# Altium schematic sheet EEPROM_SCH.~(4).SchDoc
size D
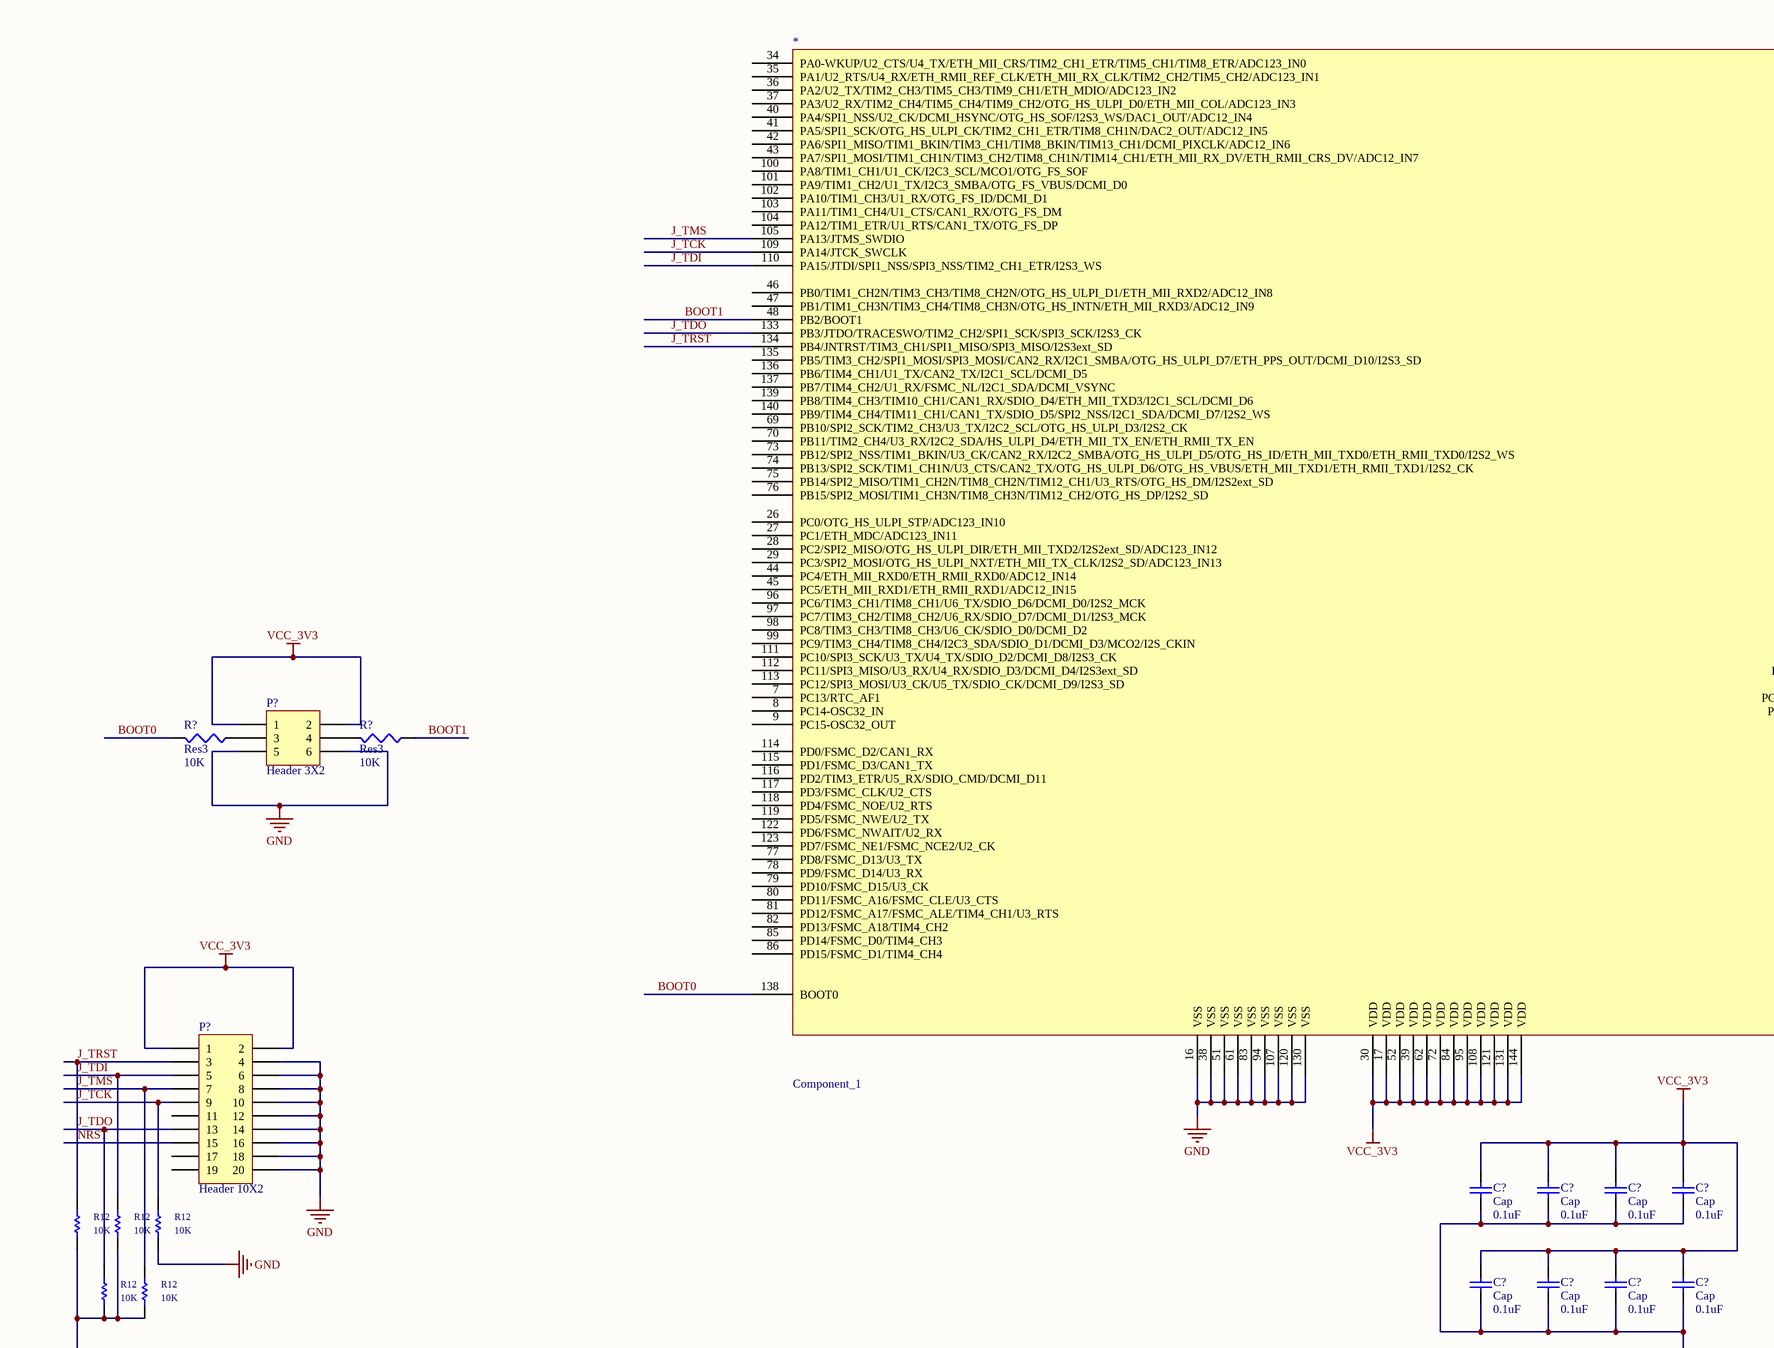
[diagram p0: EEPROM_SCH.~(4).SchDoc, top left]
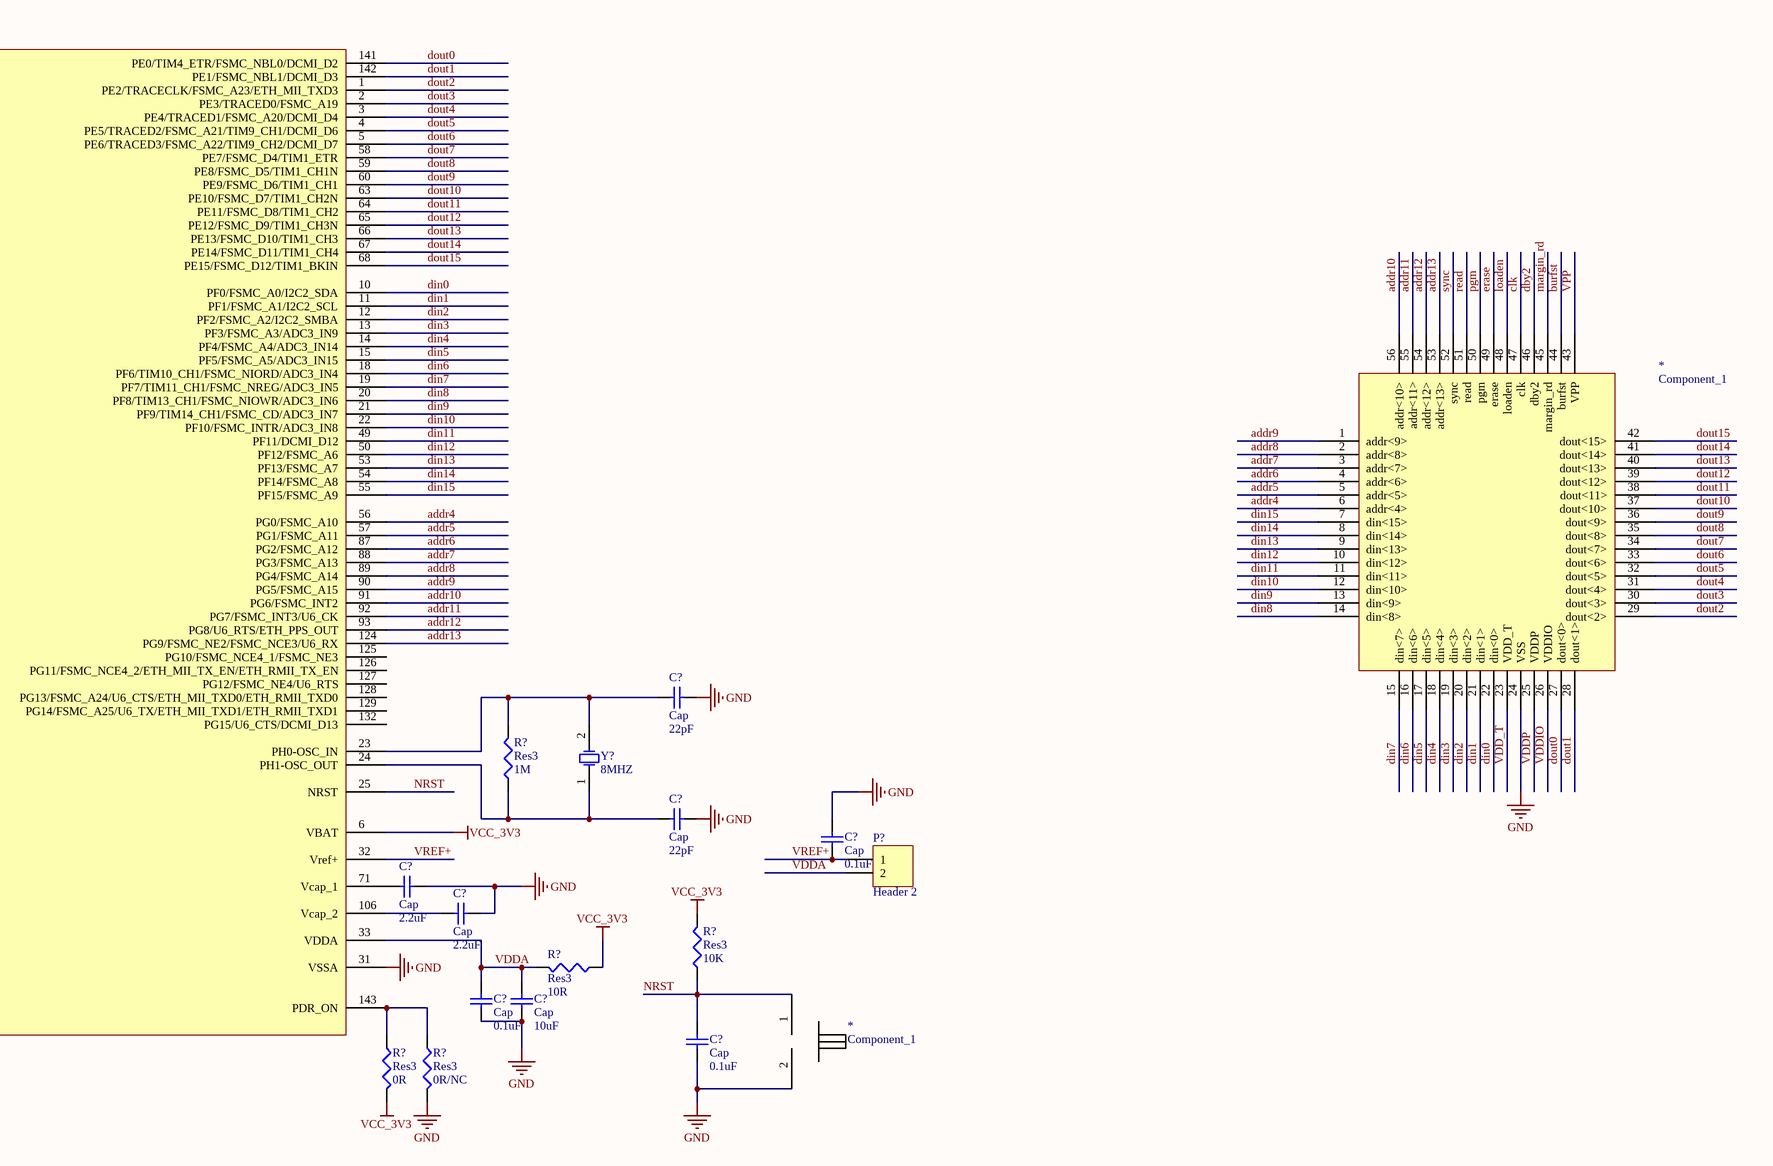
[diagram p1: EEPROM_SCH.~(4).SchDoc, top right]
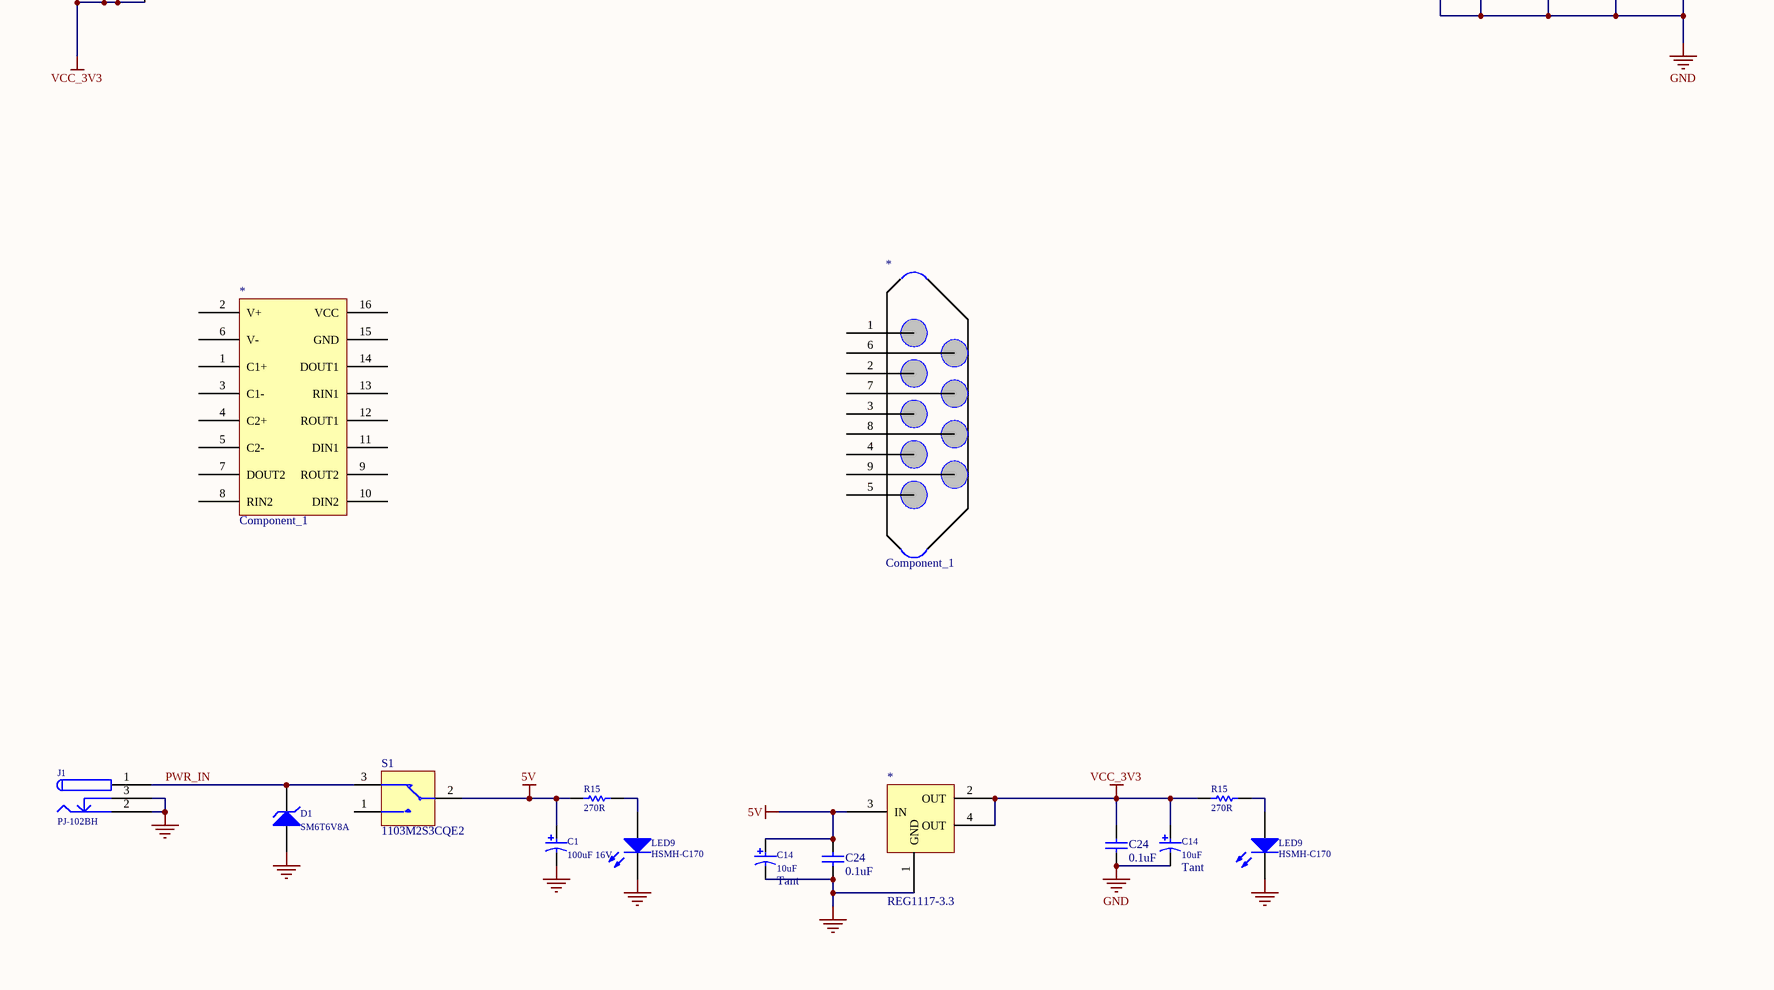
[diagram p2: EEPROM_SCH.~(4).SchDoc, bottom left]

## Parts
(Parts that share a designator on the sheet are numbered #1, #2 ... from top to bottom, then left to right.)
*#1  Component_1  [STM32F407ZET6_LCC144]
*#2  Component_1
*#3  Component_1
*#4  Component_1
*#5  Component_1
*#6  REG1117-3.3  [PCBComponent_1]
C1  100uF 16V  [CAPPR2-5X6.8]
C14#1  10uF  Capacitor Type: Tant  [MCCT-B]
C14#2  10uF  Capacitor Type: Tant  [MCCT-B]
C24#1  0.1uF  [CC2012-0805]
C24#2  0.1uF  [CC2012-0805]
C?#1  Cap  value 22pF  [RAD-0.3]
C?#2  Cap  value 22pF  [RAD-0.3]
C?#3  Cap  value 0.1uF  [RAD-0.3]
C?#4  Cap  value 2.2uF  [RAD-0.3]
C?#5  Cap  value 2.2uF  [RAD-0.3]
C?#6  Cap  value 0.1uF  [RAD-0.3]
C?#7  Cap  value 10uF  [RAD-0.3]
C?#8  Cap  value 0.1uF  [RAD-0.3]
C?#9  Cap  value 0.1uF  [RAD-0.3]
C?#10  Cap  value 0.1uF  [RAD-0.3]
C?#11  Cap  value 0.1uF  [RAD-0.3]
C?#12  Cap  value 0.1uF  [RAD-0.3]
C?#13  Cap  value 0.1uF  [RAD-0.3]
C?#14  Cap  value 0.1uF  [RAD-0.3]
C?#15  Cap  value 0.1uF  [RAD-0.3]
C?#16  Cap  value 0.1uF  [RAD-0.3]
D1  SM6T6V8A  [PCBComponent_1]
J1  PJ-102BH  [PCBComponent_1]
LED9#1  HSMH-C170  [SMD _LED]
LED9#2  HSMH-C170  [SMD _LED]
P?#1  Header 3X2  [PCBComponent_1]
P?#2  Header 2  [HDR1X2]
P?#3  Header 10X2  [HDR2X10]
R12#1  10K  [CC2012-0805]
R12#2  10K  [CC2012-0805]
R12#3  10K  [CC2012-0805]
R12#4  10K  [CC2012-0805]
R12#5  10K  [CC2012-0805]
R15#1  270R  [CR2012-0805]
R15#2  270R  [CR2012-0805]
R?#1  Res3  value 10K  [J1-0603]
R?#2  Res3  value 10K  [J1-0603]
R?#3  Res3  value 1M  [J1-0603]
R?#4  Res3  value 10K  [J1-0603]
R?#5  Res3  value 10R  [J1-0603]
R?#6  Res3  value 0R  [J1-0603]
R?#7  Res3  value 0R/NC  [J1-0603]
S1  1103M2S3CQE2  [PCBComponent_1]
Y?  8MHZ  [R38]

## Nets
5V: *#6.3(IN) C1.1 C14#2.1 C24#2.2 R15#1.2 S1.2
GND: *#1.16(VSS) *#1.31(VSSA) *#1.38(VSS) *#1.51(VSS) *#1.61(VSS) *#1.83(VSS) *#1.94(VSS) *#1.107(VSS) *#1.120(VSS) *#1.130(VSS) *#2.24(VSS) *#3.2 *#6.1(GND) C1.2 C14#1.2 C14#2.2 C24#1.1 C24#2.1 C?#1.1 C?#2.1 C?#3.1 C?#4.2 C?#5.2 C?#6.2 C?#7.2 C?#8.2 C?#9.1 C?#10.1 C?#11.1 C?#12.1 C?#13.1 C?#14.1 C?#15.1 C?#16.1 D1.1(A) J1.2 J1.3 LED9#1.2(K) LED9#2.2(K) P?#1.5 P?#1.6 P?#3.4 P?#3.6 P?#3.8 P?#3.10 P?#3.12 P?#3.14 P?#3.16 P?#3.18 P?#3.20 R12#3.2 R?#7.2
VCC_3V3: *#1.6(VBAT) *#1.17(VDD) *#1.30(VDD) *#1.39(VDD) *#1.52(VDD) *#1.62(VDD) *#1.72(VDD) *#1.84(VDD) *#1.95(VDD) *#1.108(VDD) *#1.121(VDD) *#1.131(VDD) *#1.144(VDD) *#6.2(OUT) *#6.4(OUT) C14#1.1 C24#1.2 C?#9.2 C?#10.2 C?#11.2 C?#12.2 C?#13.2 C?#14.2 C?#15.2 C?#16.2 P?#1.1 P?#1.2 P?#3.1 P?#3.2 R12#1.2 R12#2.2 R12#4.2 R12#5.2 R15#2.2 R?#4.2 R?#5.1 R?#6.2
addr4: *#1.56(PG0/FSMC_A10) *#2.6(addr<4>)
addr5: *#1.57(PG1/FSMC_A11) *#2.5(addr<5>)
addr6: *#1.87(PG2/FSMC_A12) *#2.4(addr<6>)
addr7: *#1.88(PG3/FSMC_A13) *#2.3(addr<7>)
addr8: *#1.89(PG4/FSMC_A14) *#2.2(addr<8>)
addr9: *#1.90(PG5/FSMC_A15) *#2.1(addr<9>)
addr10: *#1.91(PG6/FSMC_INT2) *#2.56(addr<10>)
addr11: *#1.92(PG7/FSMC_INT3/U6_CK) *#2.55(addr<11>)
addr12: *#1.93(PG8/U6_RTS/ETH_PPS_OUT) *#2.54(addr<12>)
addr13: *#1.124(PG9/FSMC_NE2/FSMC_NCE3/U6_RX) *#2.53(addr<13>)
BOOT0: *#1.138(BOOT0) R?#1.2
BOOT1: *#1.48(PB2/BOOT1) R?#2.1
burfst: *#2.44(burfst)
clk: *#2.47(clk)
dby2: *#2.46(dby2)
din0: *#1.10(PF0/FSMC_A0/I2C2_SDA) *#2.22(din<0>)
din1: *#1.11(PF1/FSMC_A1/I2C2_SCL) *#2.21(din<1>)
din2: *#1.12(PF2/FSMC_A2/I2C2_SMBA) *#2.20(din<2>)
din3: *#1.13(PF3/FSMC_A3/ADC3_IN9) *#2.19(din<3>)
din4: *#1.14(PF4/FSMC_A4/ADC3_IN14) *#2.18(din<4>)
din5: *#1.15(PF5/FSMC_A5/ADC3_IN15) *#2.17(din<5>)
din6: *#1.18(PF6/TIM10_CH1/FSMC_NIORD/ADC3_IN4) *#2.16(din<6>)
din7: *#1.19(PF7/TIM11_CH1/FSMC_NREG/ADC3_IN5) *#2.15(din<7>)
din8: *#1.20(PF8/TIM13_CH1/FSMC_NIOWR/ADC3_IN6) *#2.14(din<8>)
din9: *#1.21(PF9/TIM14_CH1/FSMC_CD/ADC3_IN7) *#2.13(din<9>)
din10: *#1.22(PF10/FSMC_INTR/ADC3_IN8) *#2.12(din<10>)
din11: *#1.49(PF11/DCMI_D12) *#2.11(din<11>)
din12: *#1.50(PF12/FSMC_A6) *#2.10(din<12>)
din13: *#1.53(PF13/FSMC_A7) *#2.9(din<13>)
din14: *#1.54(PF14/FSMC_A8) *#2.8(din<14>)
din15: *#1.55(PF15/FSMC_A9) *#2.7(din<15>)
dout0: *#1.141(PE0/TIM4_ETR/FSMC_NBL0/DCMI_D2) *#2.27(dout<0>)
dout1: *#1.142(PE1/FSMC_NBL1/DCMI_D3) *#2.28(dout<1>)
dout2: *#1.1(PE2/TRACECLK/FSMC_A23/ETH_MII_TXD3) *#2.29(dout<2>)
dout3: *#1.2(PE3/TRACED0/FSMC_A19) *#2.30(dout<3>)
dout4: *#1.3(PE4/TRACED1/FSMC_A20/DCMI_D4) *#2.31(dout<4>)
dout5: *#1.4(PE5/TRACED2/FSMC_A21/TIM9_CH1/DCMI_D6) *#2.32(dout<5>)
dout6: *#1.5(PE6/TRACED3/FSMC_A22/TIM9_CH2/DCMI_D7) *#2.33(dout<6>)
dout7: *#1.58(PE7/FSMC_D4/TIM1_ETR) *#2.34(dout<7>)
dout8: *#1.59(PE8/FSMC_D5/TIM1_CH1N) *#2.35(dout<8>)
dout9: *#1.60(PE9/FSMC_D6/TIM1_CH1) *#2.36(dout<9>)
dout10: *#1.63(PE10/FSMC_D7/TIM1_CH2N) *#2.37(dout<10>)
dout11: *#1.64(PE11/FSMC_D8/TIM1_CH2) *#2.38(dout<11>)
dout12: *#1.65(PE12/FSMC_D9/TIM1_CH3N) *#2.39(dout<12>)
dout13: *#1.66(PE13/FSMC_D10/TIM1_CH3) *#2.40(dout<13>)
dout14: *#1.67(PE14/FSMC_D11/TIM1_CH4) *#2.41(dout<14>)
dout15: *#1.68(PE15/FSMC_D12/TIM1_BKIN) *#2.42(dout<15>)
erase: *#2.49(erase)
J_TCK: *#1.25(NRST) *#1.105(PA13/JTMS_SWDIO) *#1.109(PA14/JTCK_SWCLK) *#1.110(PA15/JTDI/SPI1_NSS/SPI3_NSS/TIM2_CH1_ETR/I2S3_WS) *#1.133(PB3/JTDO/TRACESWO/TIM2_CH2/SPI1_SCK/SPI3_SCK/I2S3_CK) *#1.134(PB4/JNTRST/TIM3_CH1/SPI1_MISO/SPI3_MISO/I2S3ext_SD) *#3.1 C?#8.1 P?#3.3 P?#3.5 P?#3.7 P?#3.9 P?#3.13 P?#3.15 R12#1.1 R12#2.1 R12#3.1 R12#4.1 R12#5.1 R?#4.1  [also labelled J_TDI, J_TDO, J_TMS, J_TRST, NRST]
loaden: *#2.48(loaden)
margin_rd: *#2.45(margin_rd)
pgm: *#2.50(pgm)
PWR_IN: D1.2(K) J1.1 S1.3
read: *#2.51(read)
sync: *#2.52(sync)
VDD_T: *#2.23(VDD_T)
VDDA: *#1.33(VDDA) C?#6.1 C?#7.1 P?#2.2 R?#5.2
VDDIO: *#2.26(VDDIO)
VDDP: *#2.25(VDDP)
VPP: *#2.43(VPP)
VREF+: *#1.32(Vref+) C?#3.2 P?#2.1
Net*#1_23: *#1.23(PH0-OSC_IN) C?#1.2 R?#3.2 Y?.2(OSC2)
Net*#1_24: *#1.24(PH1-OSC_OUT) C?#2.2 R?#3.1 Y?.1(OSC1)
Net*#1_71: *#1.71(Vcap_1) C?#4.1
Net*#1_106: *#1.106(Vcap_2) C?#5.1
Net*#1_143: *#1.143(PDR_ON) R?#6.1 R?#7.1
NetLED9#1_1: LED9#1.1(A) R15#1.1
NetLED9#2_1: LED9#2.1(A) R15#2.1
NetP?#1_3: P?#1.3 R?#1.1
NetP?#1_4: P?#1.4 R?#2.2

Not connected (* = marked no-connect by the designer): *#1 7(PC13/RTC_AF1) 8(PC14-OSC32_IN) 9(PC15-OSC32_OUT) 26(PC0/OTG_HS_ULPI_STP/ADC123_IN10) 27(PC1/ETH_MDC/ADC123_IN11) 28(PC2/SPI2_MISO/OTG_HS_ULPI_DIR/ETH_MII_TXD2/I2S2ext_SD/ADC123_IN12) 29(PC3/SPI2_MOSI/OTG_HS_ULPI_NXT/ETH_MII_TX_CLK/I2S2_SD/ADC123_IN13) 34(PA0-WKUP/U2_CTS/U4_TX/ETH_MII_CRS/TIM2_CH1_ETR/TIM5_CH1/TIM8_ETR/ADC123_IN0) 35(PA1/U2_RTS/U4_RX/ETH_RMII_REF_CLK/ETH_MII_RX_CLK/TIM2_CH2/TIM5_CH2/ADC123_IN1) 36(PA2/U2_TX/TIM2_CH3/TIM5_CH3/TIM9_CH1/ETH_MDIO/ADC123_IN2) 37(PA3/U2_RX/TIM2_CH4/TIM5_CH4/TIM9_CH2/OTG_HS_ULPI_D0/ETH_MII_COL/ADC123_IN3) 40(PA4/SPI1_NSS/U2_CK/DCMI_HSYNC/OTG_HS_SOF/I2S3_WS/DAC1_OUT/ADC12_IN4) 41(PA5/SPI1_SCK/OTG_HS_ULPI_CK/TIM2_CH1_ETR/TIM8_CH1N/DAC2_OUT/ADC12_IN5) 42(PA6/SPI1_MISO/TIM1_BKIN/TIM3_CH1/TIM8_BKIN/TIM13_CH1/DCMI_PIXCLK/ADC12_IN6) 43(PA7/SPI1_MOSI/TIM1_CH1N/TIM3_CH2/TIM8_CH1N/TIM14_CH1/ETH_MII_RX_DV/ETH_RMII_CRS_DV/ADC12_IN7) 44(PC4/ETH_MII_RXD0/ETH_RMII_RXD0/ADC12_IN14) 45(PC5/ETH_MII_RXD1/ETH_RMII_RXD1/ADC12_IN15) 46(PB0/TIM1_CH2N/TIM3_CH3/TIM8_CH2N/OTG_HS_ULPI_D1/ETH_MII_RXD2/ADC12_IN8) 47(PB1/TIM1_CH3N/TIM3_CH4/TIM8_CH3N/OTG_HS_INTN/ETH_MII_RXD3/ADC12_IN9) 69(PB10/SPI2_SCK/TIM2_CH3/U3_TX/I2C2_SCL/OTG_HS_ULPI_D3/I2S2_CK) 70(PB11/TIM2_CH4/U3_RX/I2C2_SDA/HS_ULPI_D4/ETH_MII_TX_EN/ETH_RMII_TX_EN) 73(PB12/SPI2_NSS/TIM1_BKIN/U3_CK/CAN2_RX/I2C2_SMBA/OTG_HS_ULPI_D5/OTG_HS_ID/ETH_MII_TXD0/ETH_RMII_TXD0/I2S2_WS) 74(PB13/SPI2_SCK/TIM1_CH1N/U3_CTS/CAN2_TX/OTG_HS_ULPI_D6/OTG_HS_VBUS/ETH_MII_TXD1/ETH_RMII_TXD1/I2S2_CK) 75(PB14/SPI2_MISO/TIM1_CH2N/TIM8_CH2N/TIM12_CH1/U3_RTS/OTG_HS_DM/I2S2ext_SD) 76(PB15/SPI2_MOSI/TIM1_CH3N/TIM8_CH3N/TIM12_CH2/OTG_HS_DP/I2S2_SD) 77(PD8/FSMC_D13/U3_TX) 78(PD9/FSMC_D14/U3_RX) 79(PD10/FSMC_D15/U3_CK) 80(PD11/FSMC_A16/FSMC_CLE/U3_CTS) 81(PD12/FSMC_A17/FSMC_ALE/TIM4_CH1/U3_RTS) 82(PD13/FSMC_A18/TIM4_CH2) 85(PD14/FSMC_D0/TIM4_CH3) 86(PD15/FSMC_D1/TIM4_CH4) 96(PC6/TIM3_CH1/TIM8_CH1/U6_TX/SDIO_D6/DCMI_D0/I2S2_MCK) 97(PC7/TIM3_CH2/TIM8_CH2/U6_RX/SDIO_D7/DCMI_D1/I2S3_MCK) 98(PC8/TIM3_CH3/TIM8_CH3/U6_CK/SDIO_D0/DCMI_D2) 99(PC9/TIM3_CH4/TIM8_CH4/I2C3_SDA/SDIO_D1/DCMI_D3/MCO2/I2S_CKIN) 100(PA8/TIM1_CH1/U1_CK/I2C3_SCL/MCO1/OTG_FS_SOF) 101(PA9/TIM1_CH2/U1_TX/I2C3_SMBA/OTG_FS_VBUS/DCMI_D0) 102(PA10/TIM1_CH3/U1_RX/OTG_FS_ID/DCMI_D1) 103(PA11/TIM1_CH4/U1_CTS/CAN1_RX/OTG_FS_DM) 104(PA12/TIM1_ETR/U1_RTS/CAN1_TX/OTG_FS_DP) 111(PC10/SPI3_SCK/U3_TX/U4_TX/SDIO_D2/DCMI_D8/I2S3_CK) 112(PC11/SPI3_MISO/U3_RX/U4_RX/SDIO_D3/DCMI_D4/I2S3ext_SD) 113(PC12/SPI3_MOSI/U3_CK/U5_TX/SDIO_CK/DCMI_D9/I2S3_SD) 114(PD0/FSMC_D2/CAN1_RX) 115(PD1/FSMC_D3/CAN1_TX) 116(PD2/TIM3_ETR/U5_RX/SDIO_CMD/DCMI_D11) 117(PD3/FSMC_CLK/U2_CTS) 118(PD4/FSMC_NOE/U2_RTS) 119(PD5/FSMC_NWE/U2_TX) 122(PD6/FSMC_NWAIT/U2_RX) 123(PD7/FSMC_NE1/FSMC_NCE2/U2_CK) 125(PG10/FSMC_NCE4_1/FSMC_NE3) 126(PG11/FSMC_NCE4_2/ETH_MII_TX_EN/ETH_RMII_TX_EN) 127(PG12/FSMC_NE4/U6_RTS) 128(PG13/FSMC_A24/U6_CTS/ETH_MII_TXD0/ETH_RMII_TXD0) 129(PG14/FSMC_A25/U6_TX/ETH_MII_TXD1/ETH_RMII_TXD1) 132(PG15/U6_CTS/DCMI_D13) 135(PB5/TIM3_CH2/SPI1_MOSI/SPI3_MOSI/CAN2_RX/I2C1_SMBA/OTG_HS_ULPI_D7/ETH_PPS_OUT/DCMI_D10/I2S3_SD) 136(PB6/TIM4_CH1/U1_TX/CAN2_TX/I2C1_SCL/DCMI_D5) 137(PB7/TIM4_CH2/U1_RX/FSMC_NL/I2C1_SDA/DCMI_VSYNC) 139(PB8/TIM4_CH3/TIM10_CH1/CAN1_RX/SDIO_D4/ETH_MII_TXD3/I2C1_SCL/DCMI_D6) 140(PB9/TIM4_CH4/TIM11_CH1/CAN1_TX/SDIO_D5/SPI2_NSS/I2C1_SDA/DCMI_D7/I2S2_WS); *#4 1(C1+) 2(V+) 3(C1-) 4(C2+) 5(C2-) 6(V-) 7(DOUT2) 8(RIN2) 9(ROUT2) 10(DIN2) 11(DIN1) 12(ROUT1) 13(RIN1) 14(DOUT1) 15(GND) 16(VCC); *#5 1 2 3 4 5 6 7 8 9; P?#3 11 17 19; S1 1

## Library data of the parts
*#6 = Component_1
C1 = CAP_POLAR_1: Polar Capacitor
C14#1 C14#2 = CAP_POLAR: Polar Capacitor; AEMS Code: 2100110
C24#1 C24#2 = CAP: Capacitor
C?#1-C?#16 = Cap: Capacitor
D1 = BZG03C13: Zener Diode, 6.2V, 5W; Manufacturer: Microsemi
J1 = KLD-0202-B: Low Voltage Power Supply Connector; Manufacturer: Kycon; AEMS Code: 3510211
LED9#1 LED9#2 = HSMX-C670: Typical RED GaAs SMD LED Agilent make; AEMS Code: 2610081
P?#1 = Header 3X2: Header, 3-Pin, Dual row
P?#2 = Header 2: Header, 2-Pin
P?#3 = Header 10X2: Header, 10-Pin, Dual row
R12#1-R12#5 = RES: Resistor; AEMS Code: 1200012JT
R15#1 R15#2 = RES: Resistor; AEMS Code: 1200430
R?#1-R?#7 = Res3: Resistor
S1 = PCB_MOUNT_SWITCH: SPDT Subminiature Toggle Switch
Y? = XTAL: Crystal Oscillator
